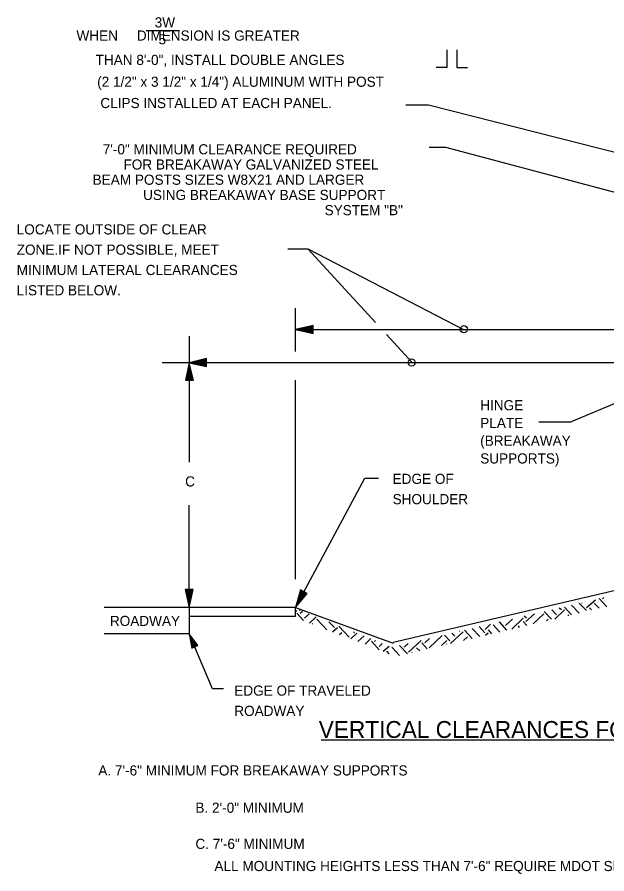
# Model space of a CAD drawing. Extents: x 139.2 to 146.5, y 202.4 to 212.6.
# Drawn here: x 139.23 to 142.71, y 207.55 to 212.61 of the extents above; entities that cross this region are included whole.
import ezdxf

# ---------------------------------------------------------------- set-up
doc = ezdxf.new("R2010")
doc.units = 0
for name, color, linetype in [('DETL-DIMS', 7, 'Continuous'), ('DETL-LINE', 7, 'Continuous'), ('DETL-NOTE', 7, 'Continuous'), ('MSHA-LOGO', 7, 'Continuous'), ('TTLB-TEXT', 7, 'Continuous')]:
    doc.layers.add(name, color=color, linetype=linetype)

msp = doc.modelspace()

# ---------------------------------------------------------------- linework, layer by layer
at = {"layer": 'DETL-DIMS'}
for p, q in [((140.9464, 211.2404), (141.8703, 210.7623)), ((140.875, 210.635), (140.875, 210.89)), ((140.875, 210.764), (142.873, 210.764)), ((140.246, 210.725), (140.246, 209.98)), ((140.261, 210.568), (140.086, 210.568)), ((142.873, 210.568), (140.273, 210.568)), ((143.214, 210.518), (142.5028, 210.2173)), ((142.3118, 210.2173), (142.5028, 210.2173)), ((140.246, 209.121), (140.246, 209.725))]:
    msp.add_line(p, q, dxfattribs=at)
for points in [[(144.0957, 211.472), (141.6601, 212.0915), (141.5263, 212.0915)], [(144.2793, 211.1696), (141.7634, 211.8414), (141.6646, 211.8414)], [(140.8294, 211.2404), (140.9464, 211.2404), (141.3472, 210.8049)], [(140.978, 210.788), (140.875, 210.764), (140.978, 210.74), (140.978, 210.788)], [(140.975, 210.785), (140.886, 210.764), (140.975, 210.743), (140.975, 210.785)], [(140.974, 210.781), (140.895, 210.764), (140.974, 210.745), (140.974, 210.781)], [(140.973, 210.778), (140.906, 210.764), (140.973, 210.749), (140.973, 210.778)], [(140.971, 210.776), (140.915, 210.764), (140.971, 210.751), (140.971, 210.776)], [(140.966, 210.774), (140.925, 210.764), (140.966, 210.753), (140.966, 210.774)], [(140.965, 210.77), (140.936, 210.764), (140.965, 210.756), (140.965, 210.77)], [(140.964, 210.766), (140.946, 210.764), (140.964, 210.76), (140.964, 210.766)], [(140.961, 210.765), (140.955, 210.764), (140.961, 210.761), (140.961, 210.765)], [(141.4127, 210.7337), (141.5624, 210.571)], [(140.271, 210.464), (140.246, 210.568), (140.224, 210.464), (140.271, 210.464)], [(140.269, 210.465), (140.246, 210.557), (140.227, 210.465), (140.269, 210.465)], [(140.348, 210.593), (140.246, 210.568), (140.348, 210.546), (140.348, 210.593)], [(140.347, 210.59), (140.258, 210.568), (140.347, 210.547), (140.347, 210.59)], [(140.346, 210.586), (140.264, 210.568), (140.346, 210.551), (140.346, 210.586)], [(140.343, 210.585), (140.275, 210.568), (140.343, 210.555), (140.343, 210.585)], [(140.342, 210.58), (140.284, 210.568), (140.342, 210.556), (140.342, 210.58)], [(140.338, 210.58), (140.295, 210.568), (140.338, 210.557), (140.338, 210.58)], [(140.337, 210.576), (140.306, 210.568), (140.337, 210.561), (140.337, 210.576)], [(140.333, 210.572), (140.317, 210.568), (140.333, 210.565), (140.333, 210.572)], [(140.331, 210.57), (140.326, 210.568), (140.331, 210.566), (140.331, 210.57)], [(140.266, 210.469), (140.246, 210.547), (140.23, 210.469), (140.266, 210.469)], [(140.264, 210.472), (140.248, 210.536), (140.232, 210.472), (140.264, 210.472)], [(140.26, 210.473), (140.248, 210.527), (140.235, 210.473), (140.26, 210.473)], [(140.256, 210.474), (140.248, 210.516), (140.239, 210.474), (140.256, 210.474)], [(140.255, 210.476), (140.248, 210.507), (140.24, 210.476), (140.255, 210.476)], [(140.252, 210.48), (140.248, 210.497), (140.243, 210.48), (140.252, 210.48)], [(140.249, 210.482), (140.248, 210.486), (140.246, 210.482), (140.249, 210.482)], [(140.875, 209.121), (141.284, 209.886), (141.365, 209.886)], [(140.222, 209.226), (140.246, 209.121), (140.269, 209.226), (140.222, 209.226)], [(140.224, 209.223), (140.246, 209.131), (140.266, 209.223), (140.224, 209.223)], [(140.228, 209.22), (140.246, 209.14), (140.264, 209.22), (140.228, 209.22)], [(140.23, 209.219), (140.246, 209.151), (140.26, 209.219), (140.23, 209.219)], [(140.233, 209.215), (140.246, 209.163), (140.258, 209.215), (140.233, 209.215)], [(140.235, 209.214), (140.246, 209.171), (140.256, 209.214), (140.235, 209.214)], [(140.239, 209.213), (140.246, 209.182), (140.253, 209.213), (140.239, 209.213)], [(140.243, 209.21), (140.246, 209.19), (140.249, 209.21), (140.243, 209.21)], [(140.244, 209.208), (140.246, 209.202), (140.248, 209.208), (140.244, 209.208)], [(140.903, 209.225), (140.875, 209.121), (140.944, 209.203), (140.903, 209.225)], [(140.905, 209.221), (140.88, 209.13), (140.94, 209.202), (140.905, 209.221)], [(140.905, 209.217), (140.885, 209.14), (140.937, 209.202), (140.905, 209.217)], [(140.907, 209.214), (140.89, 209.148), (140.933, 209.2), (140.907, 209.214)], [(140.909, 209.21), (140.895, 209.158), (140.93, 209.2), (140.909, 209.21)], [(140.91, 209.209), (140.899, 209.165), (140.925, 209.2), (140.91, 209.209)], [(140.912, 209.205), (140.903, 209.175), (140.923, 209.2), (140.912, 209.205)], [(140.912, 209.202), (140.909, 209.184), (140.92, 209.198), (140.912, 209.202)], [(140.915, 209.2), (140.912, 209.193), (140.915, 209.196), (140.915, 209.2)], [(140.449, 208.64), (140.383, 208.64), (140.245, 208.964)], [(140.297, 208.895), (140.245, 208.964), (140.261, 208.88), (140.297, 208.895)], [(140.293, 208.896), (140.248, 208.955), (140.263, 208.883), (140.293, 208.896)], [(140.291, 208.897), (140.251, 208.948), (140.264, 208.885), (140.291, 208.897)], [(140.288, 208.897), (140.255, 208.94), (140.266, 208.888), (140.288, 208.897)], [(140.286, 208.897), (140.257, 208.933), (140.266, 208.89), (140.286, 208.897)], [(140.282, 208.899), (140.261, 208.926), (140.269, 208.894), (140.282, 208.899)], [(140.281, 208.9), (140.264, 208.92), (140.27, 208.895), (140.281, 208.9)], [(140.277, 208.901), (140.268, 208.914), (140.27, 208.898), (140.277, 208.901)], [(140.274, 208.9), (140.272, 208.905), (140.272, 208.899), (140.274, 208.9)]]:
    msp.add_lwpolyline(points, dxfattribs=at)
for centre in [(141.869, 210.766), (141.5605, 210.5694)]:
    msp.add_circle(centre, 0.021, dxfattribs=at)
at = {"layer": 'DETL-LINE'}
msp.add_line((141.026, 208.3369), (143.6126, 208.3369), dxfattribs=at)
at = {"layer": 'DETL-NOTE'}
for p, q in [((139.991, 212.5325), (140.189, 212.5325)), ((141.7687, 212.4175), (141.7687, 212.3145)), ((141.8267, 212.4175), (141.8267, 212.3145)), ((141.7687, 212.3145), (141.7047, 212.3145)), ((141.8267, 212.3145), (141.8907, 212.3145))]:
    msp.add_line(p, q, dxfattribs=at)
at = {"layer": 'MSHA-LOGO'}
for p, q in [((142.551, 209.087), (142.506, 209.135)), ((142.594, 209.102), (142.551, 209.145)), ((142.566, 209.148), (142.569, 209.148)), ((142.594, 209.121), (142.646, 209.166)), ((142.668, 209.117), (142.64, 209.145)), ((142.713, 209.125), (142.668, 209.174)), ((142.688, 209.171), (142.697, 209.18)), ((140.872, 209.093), (140.882, 209.102)), ((140.921, 209.044), (140.882, 209.086)), ((140.902, 209.102), (140.897, 209.103)), ((140.902, 209.086), (140.916, 209.098)), ((142.387, 209.052), (142.344, 209.097)), ((142.416, 209.077), (142.389, 209.107)), ((142.407, 209.052), (142.463, 209.107)), ((142.446, 209.107), (142.432, 209.117)), ((142.506, 209.077), (142.463, 209.123)), ((142.624, 209.107), (142.612, 209.118)), ((140.927, 209.057), (140.955, 209.082)), ((140.957, 209.028), (140.997, 209.066)), ((141.06, 208.988), (141.001, 209.052)), ((141.104, 209.003), (141.072, 209.035)), ((142.122, 208.986), (142.079, 209.035)), ((142.116, 209.013), (142.157, 209.052)), ((142.152, 208.993), (142.219, 209.057)), ((142.241, 209.013), (142.219, 209.038)), ((142.239, 209.057), (142.226, 209.069)), ((142.236, 209.038), (142.286, 209.082)), ((142.279, 209.024), (142.341, 209.082)), ((142.357, 209.042), (142.368, 209.052)), ((142.485, 209.071), (142.49, 209.077)), ((140.976, 209.021), (140.972, 209.024)), ((141.093, 208.977), (141.122, 209.003)), ((141.104, 209.021), (141.104, 209.021)), ((141.192, 208.944), (141.13, 209.01)), ((141.918, 208.937), (141.872, 208.986)), ((141.963, 208.948), (141.918, 208.997)), ((141.993, 208.971), (141.96, 209.007)), ((141.994, 208.99), (142.027, 209.021)), ((142.035, 208.965), (142.014, 208.988)), ((142.081, 208.975), (142.042, 209.018)), ((142.197, 209.003), (142.191, 209.012)), ((141.135, 208.961), (141.147, 208.973)), ((141.202, 208.935), (141.237, 208.968)), ((141.222, 208.971), (141.216, 208.977)), ((141.243, 208.919), (141.279, 208.952)), ((141.285, 208.904), (141.319, 208.936)), ((141.639, 208.911), (141.666, 208.937)), ((141.664, 208.882), (141.741, 208.954)), ((141.787, 208.924), (141.755, 208.957)), ((141.791, 208.908), (141.865, 208.977)), ((141.816, 208.95), (141.798, 208.968)), ((141.846, 208.978), (141.843, 208.978)), ((141.866, 208.925), (141.89, 208.946)), ((141.996, 208.957), (142.012, 208.971)), ((141.369, 208.869), (141.323, 208.921)), ((141.34, 208.92), (141.346, 208.925)), ((141.369, 208.89), (141.387, 208.908)), ((141.393, 208.862), (141.427, 208.892)), ((141.489, 208.837), (141.444, 208.886)), ((141.536, 208.847), (141.489, 208.896)), ((141.516, 208.886), (141.539, 208.908)), ((141.542, 208.857), (141.616, 208.925)), ((141.609, 208.865), (141.59, 208.882)), ((141.652, 208.875), (141.621, 208.911)), ((141.639, 208.929), (141.639, 208.93)), ((141.737, 208.895), (141.768, 208.925)), ((141.768, 208.904), (141.768, 208.905)), ((141.427, 208.847), (141.413, 208.862)), ((141.564, 208.854), (141.562, 208.857))]:
    msp.add_line(p, q, dxfattribs=at)
at = {"layer": 'TTLB-TEXT'}
for p, q in [((140.875, 209.288), (140.875, 210.465)), ((145.3285, 209.8231), (141.452, 208.914)), ((140.245, 209.121), (139.743, 209.121)), ((140.875, 209.121), (140.245, 209.121)), ((140.245, 209.121), (140.245, 209.07)), ((140.245, 209.121), (140.245, 208.964)), ((140.875, 209.121), (141.452, 208.91)), ((140.875, 209.07), (140.875, 209.121)), ((140.245, 209.07), (140.875, 209.07)), ((140.245, 208.964), (139.743, 208.964))]:
    msp.add_line(p, q, dxfattribs=at)

# ---------------------------------------------------------------- texts
at = {"layer": 'DETL-LINE'}
msp.add_text('VERTICAL CLEARANCES FOR SIGNS', height=0.100002, dxfattribs=at).set_placement((141.0114, 208.3489))
at = {"layer": 'DETL-NOTE'}
for s, p in [('3W', (140.042, 212.5505)), ('   WHEN     DIMENSION IS GREATER', (139.513, 212.4725)), ('5', (140.065, 212.4505)), ('THAN 8\'-0", INSTALL DOUBLE ANGLES', (139.693, 212.3285)), ('(2 1/2" x 3 1/2" x 1/4") ALUMINUM WITH POST', (139.702, 212.1995)), ('CLIPS INSTALLED AT EACH PANEL.', (139.721, 212.0735)), ('7\'-0" MINIMUM CLEARANCE REQUIRED', (139.735, 211.8)), ('FOR BREAKAWAY GALVANIZED STEEL ', (139.8576, 211.71)), ('BEAM POSTS SIZES W8X21 AND LARGER', (139.6753, 211.62)), ('USING BREAKAWAY BASE SUPPORT ', (139.9735, 211.53)), ('SYSTEM "B"', (141.046, 211.44)), ('LOCATE OUTSIDE OF CLEAR', (139.2266, 211.3263)), ('ZONE.IF NOT POSSIBLE, MEET', (139.2266, 211.2063)), ('MINIMUM LATERAL CLEARANCES ', (139.2266, 211.0863)), ('LISTED BELOW.', (139.2266, 210.9663)), ('HINGE', (141.9656, 210.2867)), ('PLATE', (141.9656, 210.1817)), ('(BREAKAWAY', (141.9656, 210.0767)), ('SUPPORTS)', (141.9656, 209.9717)), ('C', (140.222, 209.836)), ('EDGE OF', (141.448, 209.851)), ('SHOULDER', (141.448, 209.731)), ('ROADWAY', (139.7773, 209.011)), ('EDGE OF TRAVELED', (140.5123, 208.599)), ('ROADWAY', (140.5123, 208.479)), ('               A. 7\'-6" MINIMUM FOR BREAKAWAY SUPPORTS', (139.3746, 208.1269)), ('B. 2\'-0" MINIMUM', (140.2826, 207.9063)), ('C. 7\'-6" MINIMUM', (140.2826, 207.6927)), ('  ALL MOUNTING HEIGHTS LESS THAN 7\'-6" REQUIRE MDOT SHA OFFICE OF TRAFFIC AND SAFETY APPROVAL', (140.3506, 207.5616))]:
    msp.add_text(s, height=0.06, dxfattribs=at).set_placement(p)

doc.saveas('drawing.dxf')
